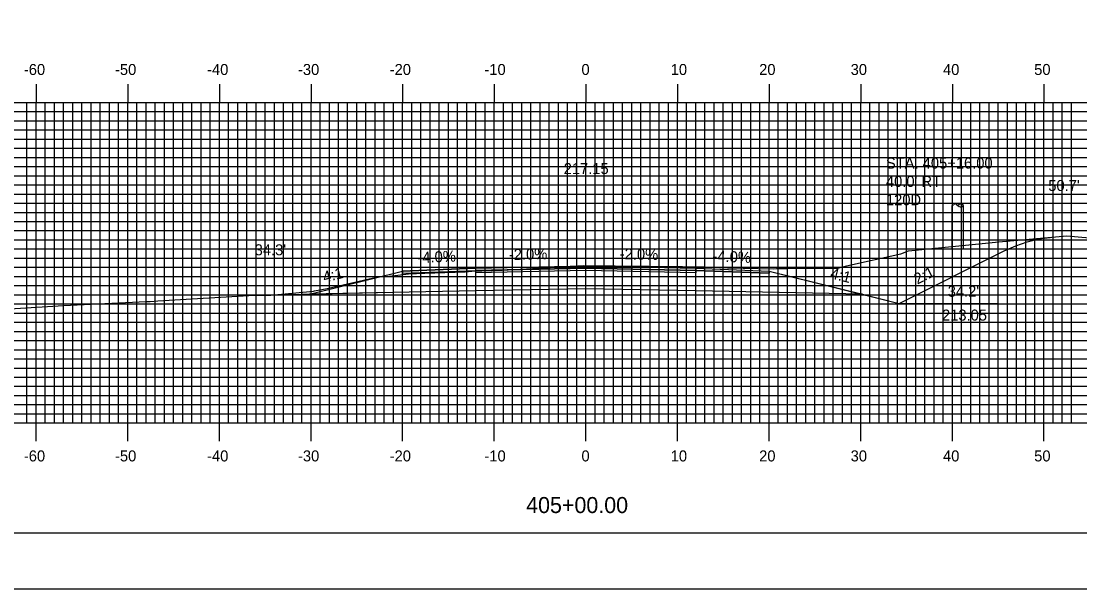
# Model space of a CAD drawing. Extents: x 851742 to 852085, y 364785 to 365005.
# Drawn here: x 851846.1 to 851961.6, y 364785.1 to 364847.1 of the extents above; entities that cross this region are included whole.
import ezdxf

# ---------------------------------------------------------------- set-up
doc = ezdxf.new("R2010")
doc.units = 0
for name, color, linetype in [('ANNOTATION', 7, 'Continuous'), ('BORDER', 7, 'Continuous'), ('D_Drainage_Text', 7, 'Continuous'), ('D_Roadway_Centerline', 7, 'Continuous'), ('D_Roadway_Centerline_Text', 7, 'Continuous'), ('D_Roadway_Edge_Shoulder', 7, 'Continuous'), ('D_Roadway_Edge_TW', 7, 'Continuous'), ('D_Roadway_Pavement', 7, 'Continuous'), ('D_Roadway_SlopeLines', 7, 'Continuous'), ('D_Roadway_SubGrade', 7, 'Continuous'), ('D_Text_Standard', 7, 'Continuous'), ('D_Utilities_Pole_Joint', 7, 'Continuous'), ('H_V ANNOTATION', 7, 'Continuous'), ('MAJOR', 7, 'Continuous'), ('MINOR', 7, 'Continuous'), ('PDRAIN', 7, 'Continuous'), ('PLOT BOUNDARY', 7, 'Continuous'), ('S_Roadway_Centerline', 7, 'Continuous')]:
    doc.layers.add(name, color=color, linetype=linetype)

msp = doc.modelspace()

# ---------------------------------------------------------------- linework, layer by layer
at = {"layer": 'ANNOTATION'}
msp.add_line((851886.62, 364817.46), (851873.39, 364817.2), dxfattribs=at)
at = {"layer": 'BORDER'}
msp.add_lwpolyline([(851758.1, 364791.23), (852078.1, 364791.23), (852078.1, 365001.23), (851758.1, 365001.23)], close=True, dxfattribs=at)
at = {"layer": 'D_Roadway_Centerline'}
msp.add_lwpolyline([(851877.53, 364817.28), (851887.7, 364819.82), (851895.7, 364820.14), (851907.7, 364820.38), (851919.7, 364820.14), (851927.7, 364819.82), (851937.88, 364817.28), (851941.88, 364816.28), (851953.37, 364822.02), (851954.62, 364822.59), (851955.87, 364823.02), (851957.12, 364823.32), (851958.37, 364823.49)], dxfattribs=at)
at = {"layer": 'D_Roadway_Edge_Shoulder'}
for points in [[(851895.7, 364820.14), (851887.7, 364819.82), (851887.7, 364819.57), (851895.7, 364819.89)], [(851919.7, 364820.14), (851927.7, 364819.82), (851927.7, 364819.57), (851919.7, 364819.89)]]:
    msp.add_lwpolyline(points, close=True, dxfattribs=at)
at = {"layer": 'D_Roadway_Edge_TW'}
msp.add_lwpolyline([(851895.7, 364819.89), (851895.7, 364820.14), (851907.7, 364820.38), (851919.7, 364820.14), (851919.7, 364819.89), (851907.7, 364820.13)], close=True, dxfattribs=at)
at = {"layer": 'D_Roadway_Pavement'}
msp.add_lwpolyline([(851895.7, 364819.64), (851895.7, 364819.89), (851907.7, 364820.13), (851919.7, 364819.89), (851919.7, 364819.64), (851907.7, 364819.88)], close=True, dxfattribs=at)
at = {"layer": 'D_Roadway_SlopeLines'}
for points in [[(851941.88, 364816.28), (851953.37, 364822.02), (851954.62, 364822.59), (851955.87, 364823.02), (851957.12, 364823.32), (851958.37, 364823.49)], [(851927.7, 364819.82), (851941.88, 364816.28)]]:
    msp.add_lwpolyline(points, dxfattribs=at)
at = {"layer": 'D_Roadway_SubGrade'}
msp.add_lwpolyline([(851895.7, 364817.64), (851877.53, 364817.28), (851887.7, 364819.82), (851887.7, 364819.57), (851895.7, 364819.89), (851907.7, 364820.13), (851919.7, 364819.89), (851927.7, 364819.57), (851927.7, 364819.82), (851937.88, 364817.28), (851919.7, 364817.64), (851907.7, 364817.88)], close=True, dxfattribs=at)
at = {"layer": 'D_Utilities_Pole_Joint'}
for p, q in [((851947.68, 364826.99), (851947.84, 364827.1)), ((851947.68, 364822.23), (851947.68, 364826.99)), ((851948.15, 364827.1), (851948.31, 364826.99)), ((851948.46, 364827.1), (851948.31, 364826.99)), ((851948.31, 364826.99), (851948.46, 364826.88)), ((851948.93, 364826.99), (851948.78, 364827.1)), ((851948.78, 364826.88), (851948.93, 364826.99)), ((851948.93, 364822.23), (851948.93, 364826.99))]:
    msp.add_line(p, q, dxfattribs=at)
for centre, start, end in [((851948, 364826.88), 90, 125.2644), ((851948, 364826.88), 54.7356, 90), ((851948.62, 364826.88), 90, 125.2644), ((851948.62, 364827.1), 234.7356, 270), ((851948.62, 364826.88), 54.7356, 90), ((851948.62, 364827.1), 270, 305.2644)]:
    msp.add_arc(centre, 0.271, start, end, dxfattribs=at)
at = {"layer": 'MAJOR'}
for p, q in [((851847.7, 364840.24), (851847.7, 364838.23)), ((851857.7, 364840.24), (851857.7, 364838.23)), ((851867.7, 364840.24), (851867.7, 364838.23)), ((851877.7, 364840.24), (851877.7, 364838.23)), ((851887.7, 364840.24), (851887.7, 364838.23)), ((851897.7, 364840.24), (851897.7, 364838.23)), ((851907.7, 364840.24), (851907.7, 364838.23)), ((851917.7, 364840.24), (851917.7, 364838.23)), ((851927.7, 364840.24), (851927.7, 364838.23)), ((851937.7, 364840.24), (851937.7, 364838.23)), ((851947.7, 364840.24), (851947.7, 364838.23)), ((851957.7, 364840.24), (851957.7, 364838.23)), ((851767.7, 364838.23), (852047.7, 364838.23)), ((851767.7, 364838.23), (852047.7, 364838.23)), ((851847.7, 364803.23), (851847.7, 364838.23)), ((851857.7, 364803.23), (851857.7, 364838.23)), ((851867.7, 364803.23), (851867.7, 364838.23)), ((851877.7, 364803.23), (851877.7, 364838.23)), ((851887.7, 364803.23), (851887.7, 364838.23)), ((851897.7, 364803.23), (851897.7, 364838.23)), ((851907.7, 364803.23), (851907.7, 364838.23)), ((851917.7, 364803.23), (851917.7, 364838.23)), ((851927.7, 364803.23), (851927.7, 364838.23)), ((851937.7, 364803.23), (851937.7, 364838.23)), ((851947.7, 364803.23), (851947.7, 364838.23)), ((851957.7, 364803.23), (851957.7, 364838.23)), ((851767.7, 364833.23), (852047.7, 364833.23)), ((851767.7, 364828.23), (852047.7, 364828.23)), ((851767.7, 364823.23), (852047.7, 364823.23)), ((851767.7, 364818.23), (852047.7, 364818.23)), ((851767.7, 364813.23), (852047.7, 364813.23)), ((851767.7, 364808.23), (852047.7, 364808.23)), ((851767.7, 364803.23), (852047.7, 364803.23)), ((851767.7, 364803.23), (852047.7, 364803.23)), ((851847.7, 364801.23), (851847.7, 364803.23)), ((851857.7, 364801.23), (851857.7, 364803.23)), ((851867.7, 364801.23), (851867.7, 364803.23)), ((851877.7, 364801.23), (851877.7, 364803.23)), ((851887.7, 364801.23), (851887.7, 364803.23)), ((851897.7, 364801.23), (851897.7, 364803.23)), ((851907.7, 364801.23), (851907.7, 364803.23)), ((851917.7, 364801.23), (851917.7, 364803.23)), ((851927.7, 364801.23), (851927.7, 364803.23)), ((851937.7, 364801.23), (851937.7, 364803.23)), ((851947.7, 364801.23), (851947.7, 364803.23)), ((851957.7, 364801.23), (851957.7, 364803.23))]:
    msp.add_line(p, q, dxfattribs=at)
at = {"layer": 'MINOR'}
for p, q in [((851846.7, 364803.23), (851846.7, 364838.23)), ((851848.7, 364803.23), (851848.7, 364838.23)), ((851849.7, 364803.23), (851849.7, 364838.23)), ((851850.7, 364803.23), (851850.7, 364838.23)), ((851851.7, 364803.23), (851851.7, 364838.23)), ((851852.7, 364803.23), (851852.7, 364838.23)), ((851853.7, 364803.23), (851853.7, 364838.23)), ((851854.7, 364803.23), (851854.7, 364838.23)), ((851855.7, 364803.23), (851855.7, 364838.23)), ((851856.7, 364803.23), (851856.7, 364838.23)), ((851858.7, 364803.23), (851858.7, 364838.23)), ((851859.7, 364803.23), (851859.7, 364838.23)), ((851860.7, 364803.23), (851860.7, 364838.23)), ((851861.7, 364803.23), (851861.7, 364838.23)), ((851862.7, 364803.23), (851862.7, 364838.23)), ((851863.7, 364803.23), (851863.7, 364838.23)), ((851864.7, 364803.23), (851864.7, 364838.23)), ((851865.7, 364803.23), (851865.7, 364838.23)), ((851866.7, 364803.23), (851866.7, 364838.23)), ((851868.7, 364803.23), (851868.7, 364838.23)), ((851869.7, 364803.23), (851869.7, 364838.23)), ((851870.7, 364803.23), (851870.7, 364838.23)), ((851871.7, 364803.23), (851871.7, 364838.23)), ((851872.7, 364803.23), (851872.7, 364838.23)), ((851873.7, 364803.23), (851873.7, 364838.23)), ((851874.7, 364803.23), (851874.7, 364838.23)), ((851875.7, 364803.23), (851875.7, 364838.23)), ((851876.7, 364803.23), (851876.7, 364838.23)), ((851878.7, 364803.23), (851878.7, 364838.23)), ((851879.7, 364803.23), (851879.7, 364838.23)), ((851880.7, 364803.23), (851880.7, 364838.23)), ((851881.7, 364803.23), (851881.7, 364838.23)), ((851882.7, 364803.23), (851882.7, 364838.23)), ((851883.7, 364803.23), (851883.7, 364838.23)), ((851884.7, 364803.23), (851884.7, 364838.23)), ((851885.7, 364803.23), (851885.7, 364838.23)), ((851886.7, 364803.23), (851886.7, 364838.23)), ((851888.7, 364803.23), (851888.7, 364838.23)), ((851889.7, 364803.23), (851889.7, 364838.23)), ((851890.7, 364803.23), (851890.7, 364838.23)), ((851891.7, 364803.23), (851891.7, 364838.23)), ((851892.7, 364803.23), (851892.7, 364838.23)), ((851893.7, 364803.23), (851893.7, 364838.23)), ((851894.7, 364803.23), (851894.7, 364838.23)), ((851895.7, 364803.23), (851895.7, 364838.23)), ((851896.7, 364803.23), (851896.7, 364838.23)), ((851898.7, 364803.23), (851898.7, 364838.23)), ((851899.7, 364803.23), (851899.7, 364838.23)), ((851900.7, 364803.23), (851900.7, 364838.23)), ((851901.7, 364803.23), (851901.7, 364838.23)), ((851902.7, 364803.23), (851902.7, 364838.23)), ((851903.7, 364803.23), (851903.7, 364838.23)), ((851904.7, 364803.23), (851904.7, 364838.23)), ((851905.7, 364803.23), (851905.7, 364838.23)), ((851906.7, 364803.23), (851906.7, 364838.23)), ((851908.7, 364803.23), (851908.7, 364838.23)), ((851909.7, 364803.23), (851909.7, 364838.23)), ((851910.7, 364803.23), (851910.7, 364838.23)), ((851911.7, 364803.23), (851911.7, 364838.23)), ((851912.7, 364803.23), (851912.7, 364838.23)), ((851913.7, 364803.23), (851913.7, 364838.23)), ((851914.7, 364803.23), (851914.7, 364838.23)), ((851915.7, 364803.23), (851915.7, 364838.23)), ((851916.7, 364803.23), (851916.7, 364838.23)), ((851918.7, 364803.23), (851918.7, 364838.23)), ((851919.7, 364803.23), (851919.7, 364838.23)), ((851920.7, 364803.23), (851920.7, 364838.23)), ((851921.7, 364803.23), (851921.7, 364838.23)), ((851922.7, 364803.23), (851922.7, 364838.23)), ((851923.7, 364803.23), (851923.7, 364838.23)), ((851924.7, 364803.23), (851924.7, 364838.23)), ((851925.7, 364803.23), (851925.7, 364838.23)), ((851926.7, 364803.23), (851926.7, 364838.23)), ((851928.7, 364803.23), (851928.7, 364838.23)), ((851929.7, 364803.23), (851929.7, 364838.23)), ((851930.7, 364803.23), (851930.7, 364838.23)), ((851931.7, 364803.23), (851931.7, 364838.23)), ((851932.7, 364803.23), (851932.7, 364838.23)), ((851933.7, 364803.23), (851933.7, 364838.23)), ((851934.7, 364803.23), (851934.7, 364838.23)), ((851935.7, 364803.23), (851935.7, 364838.23)), ((851936.7, 364803.23), (851936.7, 364838.23)), ((851938.7, 364803.23), (851938.7, 364838.23)), ((851939.7, 364803.23), (851939.7, 364838.23)), ((851940.7, 364803.23), (851940.7, 364838.23)), ((851941.7, 364803.23), (851941.7, 364838.23)), ((851942.7, 364803.23), (851942.7, 364838.23)), ((851943.7, 364803.23), (851943.7, 364838.23)), ((851944.7, 364803.23), (851944.7, 364838.23)), ((851945.7, 364803.23), (851945.7, 364838.23)), ((851946.7, 364803.23), (851946.7, 364838.23)), ((851948.7, 364803.23), (851948.7, 364838.23)), ((851949.7, 364803.23), (851949.7, 364838.23)), ((851950.7, 364803.23), (851950.7, 364838.23)), ((851951.7, 364803.23), (851951.7, 364838.23)), ((851952.7, 364803.23), (851952.7, 364838.23)), ((851953.7, 364803.23), (851953.7, 364838.23)), ((851954.7, 364803.23), (851954.7, 364838.23)), ((851955.7, 364803.23), (851955.7, 364838.23)), ((851956.7, 364803.23), (851956.7, 364838.23)), ((851958.7, 364803.23), (851958.7, 364838.23)), ((851959.7, 364803.23), (851959.7, 364838.23)), ((851960.7, 364803.23), (851960.7, 364838.23)), ((851767.7, 364837.23), (852047.7, 364837.23)), ((851767.7, 364836.23), (852047.7, 364836.23)), ((851767.7, 364835.23), (852047.7, 364835.23)), ((851767.7, 364834.23), (852047.7, 364834.23)), ((851767.7, 364832.23), (852047.7, 364832.23)), ((851767.7, 364831.23), (852047.7, 364831.23)), ((851767.7, 364830.23), (852047.7, 364830.23)), ((851767.7, 364829.23), (852047.7, 364829.23)), ((851767.7, 364827.23), (852047.7, 364827.23)), ((851767.7, 364826.23), (852047.7, 364826.23)), ((851767.7, 364825.23), (852047.7, 364825.23)), ((851767.7, 364824.23), (852047.7, 364824.23)), ((851767.7, 364822.23), (852047.7, 364822.23)), ((851767.7, 364821.23), (852047.7, 364821.23)), ((851767.7, 364820.23), (852047.7, 364820.23)), ((851767.7, 364819.23), (852047.7, 364819.23)), ((851767.7, 364817.23), (852047.7, 364817.23)), ((851767.7, 364816.23), (852047.7, 364816.23)), ((851767.7, 364815.23), (852047.7, 364815.23)), ((851767.7, 364814.23), (852047.7, 364814.23)), ((851767.7, 364812.23), (852047.7, 364812.23)), ((851767.7, 364811.23), (852047.7, 364811.23)), ((851767.7, 364810.23), (852047.7, 364810.23)), ((851767.7, 364809.23), (852047.7, 364809.23)), ((851767.7, 364807.23), (852047.7, 364807.23)), ((851767.7, 364806.23), (852047.7, 364806.23)), ((851767.7, 364805.23), (852047.7, 364805.23)), ((851767.7, 364804.23), (852047.7, 364804.23))]:
    msp.add_line(p, q, dxfattribs=at)
at = {"layer": 'PDRAIN'}
msp.add_line((851941.88, 364816.28), (851952.65, 364816.28), dxfattribs=at)
at = {"layer": 'PLOT BOUNDARY'}
msp.add_lwpolyline([(851741.92, 364785.11), (852081.92, 364785.11), (852081.92, 365005.11), (851741.92, 365005.11)], close=True, dxfattribs=at)
at = {"layer": 'S_Roadway_Centerline'}
msp.add_lwpolyline([(851844.81, 364815.69), (851850.68, 364816.07), (851859.71, 364816.48), (851860.14, 364816.48), (851860.99, 364816.58), (851871.52, 364817.17), (851873.32, 364817.19), (851877.97, 364817.63), (851878.09, 364817.65), (851879.45, 364817.93), (851885.16, 364819.22), (851885.62, 364819.18), (851885.67, 364819.18), (851888.35, 364819.52), (851890.13, 364819.57), (851894.53, 364819.74), (851895.24, 364819.79), (851898.55, 364819.9), (851903.17, 364820.16), (851907.43, 364820.43), (851910.9, 364820.37), (851918.23, 364820.3), (851920.64, 364820.27), (851923.16, 364820.16), (851923.22, 364820.16), (851928.13, 364820.05), (851928.51, 364820.08), (851929.74, 364820.08), (851930.6, 364820.12), (851934.33, 364820.14), (851935.16, 364820.14), (851935.25, 364820.14), (851935.58, 364820.23), (851936.15, 364820.38), (851942.08, 364821.69), (851942.92, 364822.04), (851952.76, 364823), (851960.21, 364823.65), (851963.91, 364823.33)], dxfattribs=at)

# ---------------------------------------------------------------- texts
at = {"layer": 'ANNOTATION'}
for s, rotation, p in [('-4.0%', 2.2906, (851889.34, 364820.69)), ('-2.0%', 1.1458, (851899.31, 364821.02)), ('-2.0%', 358.8542, (851911.39, 364821.11)), ('-4.0%', 357.7094, (851921.5, 364820.87)), ('4:1', 14.0362, (851879.15, 364818.55)), ('4:1', 345.9638, (851934.3, 364819.04)), ('2:1', 26.5651, (851943.88, 364818.33))]:
    msp.add_text(s, height=1.2, rotation=rotation, dxfattribs=at).set_placement(p)
for s, p in [("34.2'", (851947.19, 364817.01)), ('213.05', (851946.57, 364814.41))]:
    msp.add_text(s, height=1.2, dxfattribs=at).set_placement(p)
at = {"layer": 'D_Drainage_Text'}
for s, p in [('STA. 405+16.00', (851940.45, 364831.01)), ("40.0' RT.", (851940.45, 364829.01)), ('120D', (851940.45, 364827))]:
    msp.add_text(s, height=1.2, dxfattribs=at).set_placement(p)
at = {"layer": 'D_Roadway_Centerline'}
for s in ['C', 'L']:
    msp.add_text(s, height=0.0146, dxfattribs=at).set_placement((851907.7, 364820.38))
at = {"layer": 'D_Roadway_Centerline_Text'}
msp.add_text('217.15', height=1.2, dxfattribs=at).set_placement((851905.28, 364830.41))
at = {"layer": 'D_Text_Standard'}
for s, p in [("50.7'", (851958.17, 364828.56)), ("34.3'", (851871.55, 364821.54))]:
    msp.add_text(s, height=1.2, dxfattribs=at).set_placement(p)
at = {"layer": 'H_V ANNOTATION'}
for s, height, p in [('-60', 1.2, (851846.36, 364841.23)), ('-50', 1.2, (851856.31, 364841.23)), ('-40', 1.2, (851866.36, 364841.23)), ('-30', 1.2, (851876.28, 364841.23)), ('-20', 1.2, (851886.29, 364841.23)), ('-10', 1.2, (851896.63, 364841.23)), ('0', 1.2, (851907.22, 364841.23)), ('10', 1.2, (851916.96, 364841.23)), ('20', 1.2, (851926.61, 364841.23)), ('30', 1.2, (851936.6, 364841.23)), ('40', 1.2, (851946.68, 364841.23)), ('50', 1.2, (851956.63, 364841.23)), ('-60', 1.2, (851846.36, 364799.03)), ('-50', 1.2, (851856.31, 364799.03)), ('-40', 1.2, (851866.36, 364799.03)), ('-30', 1.2, (851876.28, 364799.03)), ('-20', 1.2, (851886.29, 364799.03)), ('-10', 1.2, (851896.63, 364799.03)), ('0', 1.2, (851907.22, 364799.03)), ('10', 1.2, (851916.96, 364799.03)), ('20', 1.2, (851926.61, 364799.03)), ('30', 1.2, (851936.6, 364799.03)), ('40', 1.2, (851946.68, 364799.03)), ('50', 1.2, (851956.63, 364799.03)), ('405+00.00', 1.75, (851901.18, 364793.39))]:
    msp.add_text(s, height=height, dxfattribs=at).set_placement(p)
at = {"layer": 'S_Roadway_Centerline'}
for s, p in [('L', (851907.42, 364820.43)), ('C', (851907.43, 364820.43))]:
    msp.add_text(s, height=0.0146, dxfattribs=at).set_placement(p)

doc.saveas('drawing.dxf')
